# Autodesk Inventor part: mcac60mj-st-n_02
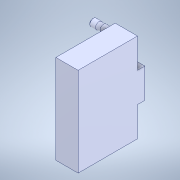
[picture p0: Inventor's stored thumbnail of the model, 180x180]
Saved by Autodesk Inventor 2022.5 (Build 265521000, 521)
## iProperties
Created: 2023-04
Part Number: mcac60mj-st-n_02
Material: Generic
Document SubType Name: Modeling
Designer: ImaoCorp
Density: 1 g/cm^3
Appearance: Default
Author: ImaoCorp
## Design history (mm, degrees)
feature "mcac60mj-st-n_02"
node "ソリッド1"
